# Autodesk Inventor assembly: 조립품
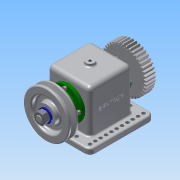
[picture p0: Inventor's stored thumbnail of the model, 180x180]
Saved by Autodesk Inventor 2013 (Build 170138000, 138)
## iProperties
Created: 2018-11
Part Number: 조립품
Document SubType Name: Assembly
Designer: Administrator
Author: Administrator
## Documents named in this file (13)
- C:\Users\Administrator\Desktop\481107V1022\조립품.iam
- C:\Users\Administrator\Desktop\481107V1022\본체.ipt
- C:\Users\Administrator\Desktop\481107V1022\V벨트풀리.ipt
- C:\Users\Administrator\Desktop\481107V1022\너트 M12x1.25.ipt
- C:\Users\Administrator\Desktop\481107V1022\베어링 6203.ipt
- C:\Users\Administrator\Desktop\481107V1022\볼트 M4.ipt
- C:\Users\Administrator\Desktop\481107V1022\부시.ipt
- C:\Users\Administrator\Desktop\481107V1022\스퍼기어.ipt
- C:\Users\Administrator\Desktop\481107V1022\오일 실 26 38 8.ipt
- C:\Users\Administrator\Desktop\481107V1022\와셔 12x24.ipt
- C:\Users\Administrator\Desktop\481107V1022\축.ipt
- C:\Users\Administrator\Desktop\481107V1022\커버.ipt
- C:\Users\Administrator\Desktop\481107V1022\키 5x5x12.ipt
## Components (1 placed, 1 different names)
1. V벨트풀리:1
